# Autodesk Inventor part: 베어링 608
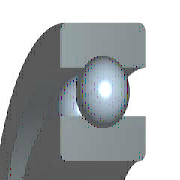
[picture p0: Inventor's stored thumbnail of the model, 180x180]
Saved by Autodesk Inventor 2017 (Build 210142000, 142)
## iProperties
IsCustomPart: 1
Created: 2012-02
Part Number: 베어링 608
Material: 강철, 연강
Description: 깊은 그루브 볼 베어링
Document SubType Name: Modeling
Standard: KS B 2023
Designer: mduedu
Standards Organization: KS
Language: ko-KR
Size Designation: 608 - 8 x 22 x 7
Categories: <MemberInstance><Categories><Category DisplayName="샤프트 부품" InternalName="7f7aeb1f-a693-4053-b835-cee3144e0d98" Mnemonic="SHFT"><Category DisplayName="베어링" Inter
Density: 7.85 g/cm^3
Appearance: 주황색
Mass: 12.145 g
Surface Area: 20.0754 cm^2
Volume: 1.54714 cm^3
Author: mduedu
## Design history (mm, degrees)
sketch "스케치" dims "d0" = 3.64 (= -0.26 x WD + 0.26 x BD)
  geometry: L1 (1.68, 7.5)-(5.32, 7.5); L2 (3.5, 7.5)-(3.5, 5.68); L3 (3.5, 7.5)-(3.5, 9.32); L4 (2.148, 6.282)-(0, 6.282); L5 (0, 4)-(7, 4); L6 (2.148, 8.718)-(0, 8.718); L7 (0, 11)-(7, 11); L8 (7, 4)-(7, 6.282); L9 (4.852, 6.282)-(7, 6.282); L10 (4.852, 8.718)-(7, 8.718); L11 (7, 11)-(7, 8.718); L12 (-1.4, 0)-(8.4, 0) reference; L13 (0, -0.3)-(0, 5.3) reference
  constraints: 22 end point, 4 point on line, 2 collinear, 2 perpendicular, 2 symmetric about line, 1 midpoint, 1 parallel, 14 other
  dimensions: "d9" = 8 diameter of L5 L12 (= WD); "d11" = 22 diameter of L7 L12 (= BD); "d12" = 7 distance between parallel lines of L8 L13 (= KB); "d13" = 12.564 diameter of L9 L12 (= 0.326 x BD + 0.674 x WD)
revolve "본체" stored, may be unused: angle "d6" = 90 deg
revolve "볼" stored, may be unused: angle "d7" = 90 deg
pattern_circular "IDS_ARRAYBALL[SIMPL:T]" dims angle "d3" = 360 deg
body "Solid1"
fillet "모깎기1" dims "d1" = 0.3 (= KRS)
other parameters: "WD" = 8 [user parameter; used in 5 equation terms], "BD" = 22 [user parameter; used in 5 equation terms], "KB" = 7 [user parameter; used in 1 equation term], "KRS" = 0.3 [user parameter; used in 1 equation term], "d4" = 0, "d5" = 0, "d8" = 0, "d14" = 0, "d15" = 0, "BBA" = 0 [user parameter], "BC0" = 1370000 [user parameter], "BC" = 3250000 [user parameter], "BR" = 11 (= 0.5 x BD) [user parameter], "WR" = 4 (= 0.5 x WD) [user parameter]
